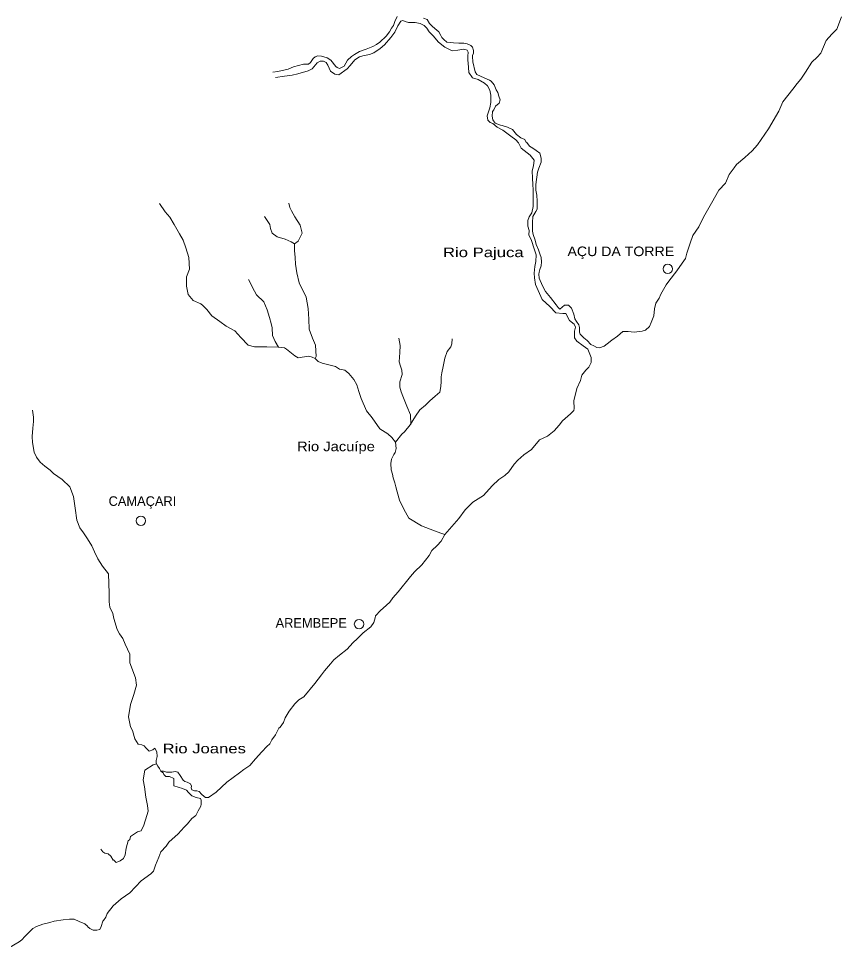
# Model space of a CAD drawing. Extents: x 47169 to 972804, y 7447977 to 9608469.
# Drawn here: x 564823 to 622022, y 8566017 to 8630617 of the extents above; entities that cross this region are included whole.
import ezdxf

# ---------------------------------------------------------------- set-up
doc = ezdxf.new("R2010")
doc.units = 0
doc.header["$LTSCALE"] = 270
doc.layers.add('1', color=7, linetype='Continuous', lineweight=13)
doc.layers.add('2', color=7, linetype='Continuous', lineweight=13)
doc.layers.add('3', color=7, linetype='Continuous')

msp = doc.modelspace()

# ---------------------------------------------------------------- linework, layer by layer
at = {"layer": '1'}
for points in [[(582501.5, 8626884.5), (582849.4, 8626927.8), (583556.5, 8627102.7), (583926.5, 8627256.4), (584622.8, 8627442.4), (584981.5, 8627441.4), (585123.2, 8627562.6), (585308.8, 8627838.5), (585428.7, 8627959.8), (585613.7, 8628014.6), (585885.4, 8628002.7), (586276.4, 8627879.9), (586536.8, 8627724.3), (586883.3, 8627280.9), (586970.1, 8627203.2), (587133, 8627147.4), (587448.7, 8627312.4), (587689.1, 8627720.8), (587972.5, 8627974.4), (588168.6, 8628128.6), (588528, 8628337.6), (588985.1, 8628491.1), (589442.2, 8628666.6), (589714.4, 8628820.6), (589943.2, 8628974.7), (590368.5, 8629393.7), (590608.6, 8629691.5), (590750.7, 8629945.4), (590892.7, 8630144.1), (590969.6, 8630409.2), (591144.7, 8630762.6)], [(592959.9, 8630646.2), (593231.3, 8630545.8), (593393.6, 8630279.9), (593599.4, 8630058), (593903, 8629813.7), (594044, 8629702.7), (594184.5, 8629436.8), (594249.3, 8629303.9), (594379.3, 8629159.7), (594585.2, 8628971), (595052.5, 8628925.2), (595422.1, 8628913), (595780.8, 8628911.8), (595998.1, 8628855.8), (596258.6, 8628733.2), (596377.8, 8628622.3), (596442.3, 8628400.8), (596441.7, 8628212.8), (596386.8, 8628047.1), (596375.6, 8627969.8), (596407, 8627604.7), (596556.9, 8626907.4), (596675.8, 8626719), (597196.9, 8626507.1), (597566, 8626340), (597663.6, 8626273.3), (597880.1, 8626007.1), (598031.1, 8625663.8), (598139.1, 8625464.3), (598203.6, 8625231.9), (598311.3, 8624955), (598223.6, 8624734.1), (597972.9, 8624535.9), (597852.5, 8624270.9), (597765.1, 8624149.5), (597753.1, 8623828.8), (597795.8, 8623574.3), (597958, 8623341.5), (598316.2, 8623207.6), (598435.7, 8623174), (598815.8, 8623073.1), (599163, 8622895), (599444.4, 8622551.2), (599726.2, 8622317.9), (600008.4, 8622206.4), (600083.9, 8622040.2), (600149, 8622006.8), (600343.7, 8621740.7), (600571.5, 8621607.2), (600810, 8621440.4), (601048.4, 8621251.6), (601155.9, 8620897.3), (601155, 8620631.9), (600990.5, 8620223.2), (600891.6, 8619925), (600780, 8619073.8), (600778.6, 8618686.7), (600842.6, 8618332.5), (600862.8, 8617912.2), (600861.6, 8617547.2), (600860.9, 8617359.2), (600773.4, 8617193.6), (600718.7, 8617083.2), (600576.6, 8616851.4), (600542.5, 8616431.3), (600540.4, 8615823)], [(600540.4, 8615823), (600604.8, 8615601.6), (600744.7, 8615202.9), (600808.8, 8614904.1), (600959.7, 8614538.6), (601056.4, 8614250.7), (601142.5, 8614007.1), (601163.2, 8613697.3), (601140.5, 8613432), (601063.5, 8613166.8), (601008.5, 8612990), (600986.3, 8612835.3), (601017.9, 8612558.7), (601244.2, 8612027), (601460.1, 8611628.1), (601806.3, 8611228.7), (602195.6, 8610718.6), (602336.2, 8610519), (602455.2, 8610396.9), (602618.7, 8610540.1), (602771.3, 8610683.3), (603042.9, 8610682.3), (603270.3, 8610471.4), (603410.1, 8610050.6), (603485, 8609740.6), (603603.8, 8609541.1), (603776.7, 8609308.2), (603808.7, 8609131.2), (603807.5, 8608799.4), (603872.2, 8608666.4), (604121.1, 8608411.1), (604348.6, 8608222.3), (604608.3, 8607944.8), (604803.5, 8607855.6), (605009.5, 8607744.3), (605204.9, 8607710.4), (605520.4, 8607830.9), (605738.3, 8607996), (606054.3, 8608249.2), (606457.3, 8608524.2), (606838.7, 8608843.5), (607208.1, 8608853.2), (607610, 8608818.5), (608164.2, 8608871.7), (608403.5, 8608948.2), (608676.1, 8609190.5), (608796.7, 8609477.6), (608972.3, 8609941.4), (609028.4, 8610427.9), (609116.8, 8610814.7), (609357.2, 8611178.7), (609467, 8611454.8), (609849.7, 8612094.8), (610013.7, 8612359.6), (610570.6, 8613076.4), (610942.1, 8613616.9), (611182.4, 8613936.7), (611281.6, 8614301.3), (611501.6, 8614986.2), (611699.3, 8615527.4), (612103.8, 8616134.1), (612443.3, 8616807.5), (612979.5, 8617767.6), (613504.8, 8618672.5), (613963.2, 8619179.4), (614226.4, 8619764.6), (614576, 8620238.8), (614740, 8620459.3), (615307.2, 8620965.8), (615808.9, 8621417.3), (616180.1, 8621825), (616945.5, 8622939), (617668, 8624185.9), (617942.4, 8624837.4), (618292.1, 8625278.3), (618652.6, 8625708.2), (618936.8, 8626094.2), (619198.9, 8626391.7), (619527.1, 8626888.1), (619975.7, 8627594.1), (620325, 8627924.4), (620598, 8628210.9), (620971.3, 8629083.1), (621364.5, 8629523.9), (621692.2, 8629887.5), (622022, 8630748.8)], [(600312.4, 8615879.1), (600226.5, 8616178), (600227.9, 8616576.2), (600315.7, 8616819.2), (600490.5, 8617106.1), (600589.9, 8617548.2), (600592.5, 8618289.2), (600583.1, 8618709.5), (600562.7, 8619085.6), (600542.5, 8619528), (600522.5, 8620025.8), (600610.6, 8620368.3), (600666.4, 8620777.4), (600374.1, 8621121.2), (599973.1, 8621443.4), (599767.2, 8621610), (599583.7, 8621964.5), (599399.6, 8622175.3), (599052.7, 8622441.9), (598488.9, 8622853.1), (598087.5, 8623064.6), (597784, 8623308.9), (597599.5, 8623398), (597447.9, 8623553.3), (597394.6, 8623863.2), (597592, 8624404.5), (597658.5, 8624769.2), (597649.4, 8625300.1), (597585.3, 8625632.1), (597412.4, 8625942.4), (597206.5, 8626131.1), (596772.5, 8626375.8), (596370.8, 8626498.8), (596122, 8626875.7), (596069.8, 8627539.4), (596059.5, 8627705.4), (596060.5, 8627992.9), (596083.1, 8628269.3), (596007.5, 8628424.4), (595768.6, 8628480.5), (595366.1, 8628415.5), (594963.7, 8628372.6), (594442.7, 8628617.6), (594009.1, 8628983.9), (593651.7, 8629427.5), (593359.1, 8629693.8), (593207.7, 8629948.7), (593023.5, 8630137.3), (592741.3, 8630282), (592393.6, 8630338.4), (591937, 8630350.9), (591698, 8630418), (591535.2, 8630484.9), (591404.5, 8630430), (591175.2, 8630121.1), (590989, 8629668.2), (590694.3, 8629293.1), (590257.9, 8628796.8), (589952.7, 8628532.3), (589527.8, 8628235), (589223.1, 8628125.4), (588744.5, 8628027.3), (588516, 8627961.6), (588200.1, 8627741.4), (587883.7, 8627355.3), (587654.6, 8627112.7), (587088.2, 8626705.2), (586805.7, 8626761.3), (586512.8, 8626950.2), (586329.2, 8627382.1), (586199.3, 8627559.4), (586014.8, 8627648.5), (585786.5, 8627649.1), (585579.7, 8627550.2), (585219.7, 8627119.9), (584958.4, 8626976.9), (584229.5, 8626768.9), (583837.9, 8626670.6), (583305, 8626605.7), (582685.2, 8626530.1)], [(594450.5, 8594741.7), (594168.4, 8594820.1), (593431, 8595110), (592834.6, 8595344.3), (591956.8, 8595878), (591708.3, 8596288), (591460.2, 8596775.4), (591309.3, 8597129.8), (591137.4, 8597694.4), (591051.6, 8598048.6), (590976.5, 8598325.4), (590869, 8598679.6), (590804.7, 8598934.2), (590729.7, 8599244.1), (590698.4, 8599664.5), (590742.9, 8599985.1), (590906.8, 8600305.3), (591005, 8600448.7), (591081.9, 8600713.9), (591029, 8601145.4), (590769.4, 8601489.1), (590487.8, 8601733.3), (589924.1, 8602077.9), (589405.2, 8602853.8), (589004.9, 8603341.6), (588627.4, 8604183.3), (588476.9, 8604681.5), (588337.1, 8605146.4), (588121, 8605523.1), (587785.6, 8605933.4), (587503.8, 8606166.5), (587134.8, 8606245), (586852.9, 8606411.8), (586483.8, 8606512.4), (585919.4, 8606657.9), (585637.3, 8606758.3), (585431.6, 8606980.1), (585236.3, 8607069.2), (584997.5, 8607136.2), (584541.1, 8607060.2), (584269.4, 8607016.8), (584030.8, 8607161.2), (583445.6, 8607616.4), (583304.7, 8607727.4), (582892, 8607761.8), (582088.2, 8607786.2), (581230, 8607777.6), (580785, 8607911.6), (580265, 8608432.8), (579853.5, 8608898.5), (579257, 8609231.9), (578812.4, 8609542.8), (578248.6, 8609953.6), (577913.1, 8610385.8), (577631.3, 8610663), (577490.4, 8610785.1), (576958.7, 8611007.7), (576601.3, 8611417.8), (576494.2, 8612004.3), (576506.8, 8612656.7), (576714.7, 8613198.1), (576651.7, 8614005.6), (576457.9, 8614680.7), (576252.8, 8615201), (576004.1, 8615644.1), (575636.4, 8616297.5), (575333.4, 8616796), (575008.4, 8617172.8), (574618.8, 8617760)], [(583999.4, 8614958.2), (584249.8, 8615145.5), (584359, 8615311.1), (584534, 8615697.6), (584405.2, 8616239.9), (584037.5, 8616838.2), (583788.8, 8617248.1), (583680.8, 8617480.7), (583616.5, 8617790.5)], [(585431.6, 8606980.1), (585508, 8607123.7), (585456, 8607898), (585251.1, 8608385.2), (585024.8, 8609016.3), (584994.3, 8609702.1), (584953.1, 8610454.2), (584814.2, 8611239.8), (584317.3, 8612236.7), (584167.2, 8612922.8), (584071.3, 8613542.4), (584040, 8613995.9), (584008.9, 8614493.7), (583999.4, 8614958.2), (583760.7, 8615080.6), (583348.3, 8615269.8), (582794.7, 8615448.3), (582447.7, 8615681.6), (582329.1, 8616024.8), (582286.4, 8616301.4), (581918.6, 8616844.3)], [(577548.8, 8576666.6), (577732.9, 8576522.3), (577819.5, 8576444.7), (578025.7, 8576455.2), (578569.2, 8576807.5), (579298.2, 8577513.3), (580189.8, 8578152.2), (580472.7, 8578383.6), (580896.7, 8578670), (581299.6, 8579133.3), (581735.1, 8579629.7), (582083.4, 8579993.7), (582279.3, 8580181.1), (582421.2, 8580457.2), (582671.8, 8580799.3), (582922.8, 8581263), (582999, 8581329.2), (583227.9, 8581671.3), (583359.1, 8581980.6), (583642.7, 8582455.3), (584034.9, 8582951.8), (584296.2, 8583227.6), (584655, 8583436.6), (585406.7, 8584374.4), (585875.3, 8584981.2), (586093.2, 8585246), (586507.2, 8585742.4), (586746.9, 8586018.2), (587138.7, 8586348.8), (587671.8, 8586756.3), (588064, 8587197.5), (588379.8, 8587506.2), (588771.8, 8587892), (589305.1, 8588321.7), (589512.3, 8588619.6), (589600.2, 8588951.1), (589622.3, 8589072.7), (589970.9, 8589458.7), (590166.8, 8589612.9), (590624.1, 8590020.6), (590842.2, 8590329.6), (591201.8, 8590737.7), (592063, 8591818.7), (592346.3, 8592127.5), (592847.3, 8592623.5), (593359.8, 8593274.3), (593545.5, 8593616.6), (593926.7, 8593969.2), (594199.2, 8594278), (594450.5, 8594741.7), (595431.5, 8595855.4), (595857, 8596451.2), (596390.9, 8596991.3), (597130.9, 8597442.3), (597741.3, 8598114.8), (598199, 8598566.7), (598623.5, 8598841.7), (598895.8, 8599084.1), (599277.9, 8599635.8), (599539.5, 8599911.3), (599953.5, 8600285.9), (600486.9, 8600638), (601043.2, 8601310.7), (601598.1, 8601585.2), (602055.6, 8601937.4), (602393.7, 8602334.4), (602633.8, 8602643.2), (603200.3, 8603127.8), (603418.3, 8603348.2), (603440.6, 8603503), (603420.8, 8604033.9), (603630.3, 8604895.8), (603882.2, 8605447.9), (603970.5, 8605823.6), (604254.2, 8606165.5), (604461.3, 8606374.8), (604614.6, 8606706.1), (604626.7, 8607037.8), (604389.8, 8607613.8), (604064.8, 8607847.3), (603631.4, 8608180.7), (603469.3, 8608413.5), (603460.1, 8608878.1), (603526.4, 8609165.4), (603451, 8609353.7), (603115.1, 8609609.2), (602856.1, 8610096.8), (602649.8, 8610108.6), (602171.8, 8610143.5), (601749.8, 8610598.5), (601230, 8611087), (600766.5, 8612128.2), (600681.1, 8612582), (600671.4, 8612913.8), (600705.7, 8613378.2), (600783, 8613731.8), (600806.3, 8614174.2), (600666.5, 8614606), (600483.8, 8615181.7), (600300.5, 8615580.5), (600312.4, 8615879.1)], [(582892, 8607761.8), (582665, 8608160.6), (582481.5, 8608581.3), (582450.5, 8609112.3), (582375.3, 8609400.1), (582257, 8609820.7), (582106.4, 8610363), (581869, 8610916.7), (581370.7, 8611404.7), (581089.7, 8611925.3), (580916.8, 8612268.6), (580808.7, 8612479)], [(591029, 8601145.4), (591465.2, 8601719.1), (591639.5, 8601873.4), (592053.8, 8602358.7), (592425.1, 8602965.8), (592708.9, 8603407.2), (593101, 8603726.7), (593406.1, 8604024.3), (593776.5, 8604354.9), (594103.2, 8604630.3), (594169.8, 8605039.3), (594203.4, 8605371), (594204.5, 8605691.7), (594238, 8605968.1), (594348.1, 8606410.1), (594447.8, 8606995.9), (594612.3, 8607470.9), (594863.2, 8607790.9), (594950.8, 8608000.7), (594973.7, 8608354.5)], [(592053.8, 8602358.7), (592086.5, 8602380.7), (592077.8, 8603066.4), (591819, 8603653.4), (591538.9, 8604362.2), (591409.5, 8604661.2), (591334.6, 8604993.2), (591335.7, 8605358.2), (591489.5, 8605866.4), (591468.7, 8606165.1), (591361, 8606453), (591285.9, 8606751.8), (591320.5, 8607393.2), (591354.7, 8607868.7), (591258.5, 8608388.8)], [(574721.1, 8578277.9), (574613.1, 8578466.3), (574494.1, 8578632.5), (574386.1, 8578820.8), (574397.5, 8579019.8), (574463.3, 8579285.1), (574431.7, 8579628), (574291.2, 8579871.7), (574149.8, 8579750.4), (573910.9, 8579673.6), (573672.8, 8579906.5), (573553.7, 8580039.5), (573380.3, 8580106.3), (573130.8, 8580162.3), (572903.8, 8580516.8), (572731.8, 8581114.4), (572613.1, 8581369.1), (572473.7, 8582044.1), (572595.4, 8582917.4), (572835.9, 8583602.5), (573022.1, 8584254.5), (572958.3, 8584763.4), (572559.5, 8585815.1), (572561, 8586423.4), (572237.1, 8587098.8), (572064.5, 8587497.4), (571848.2, 8587829.7), (571675.3, 8588117.7), (571449.3, 8588892.4), (571363.3, 8589235.5), (571158.2, 8589678.4), (571126.5, 8590043.4), (571117.2, 8590651.7), (571077.2, 8592001.1), (570666, 8592544), (570330.7, 8593042.5), (570103.9, 8593540.7), (569920.3, 8593950.4), (569617.5, 8594437.7), (569336.2, 8594847.6), (569076.5, 8595202.2), (568860.7, 8595733.5), (568754.1, 8596574.3), (568647.5, 8597381.8), (568388.5, 8598057.1), (567846.8, 8598567.1), (567261.3, 8598966.6), (567012.2, 8599210.5), (566643.6, 8599487.9), (566329.3, 8599765.1), (566058.6, 8600108.6), (565907.4, 8600462.8), (565800.3, 8601126.6), (565768.8, 8601558), (565813.5, 8602121.9), (565858.1, 8602597.3), (565858.7, 8602895.9), (565794.7, 8603382.7)], [(564188.7, 8566017.2), (564862.1, 8566413.8), (565046.8, 8566546.1), (565264.2, 8566777.8), (565514.3, 8567031.6), (565818.8, 8567340.6), (566068.6, 8567472.7), (566513.7, 8567626.4), (567002.1, 8567746.9), (567306, 8567845.7), (567913.7, 8567932.7), (568358.6, 8567986.9), (568684, 8567986.1), (569030.7, 8567830.4), (569420.8, 8567663.5), (569604.8, 8567497.2), (569648.1, 8567452.8), (569777.9, 8567341.9), (570005.4, 8567219.7), (570265.8, 8567219), (570472, 8567273.8), (570559.2, 8567461.6), (570668.7, 8567837.3), (570723, 8567892.5), (570897.2, 8568124.3), (570973.8, 8568367.4), (571398.2, 8568908.2), (571952.7, 8569404.5), (572561.3, 8569812.1), (573333.7, 8570639.5), (574007.6, 8571124.4), (574192.5, 8571322.9), (574334.7, 8571731.8), (574564, 8572295.2), (574706, 8572670.8), (575076, 8573068), (575272, 8573343.9), (575913.7, 8573928.3), (576338.1, 8574391.7), (576566.6, 8574601.2), (576860.6, 8574976.4), (577143.3, 8575196.8), (577296.1, 8575517.1), (577481.4, 8575848.4), (577514.4, 8575981), (577515.1, 8576257.5), (577461.2, 8576379.3), (577157.6, 8576446.5), (576875.8, 8576568.9), (576637.7, 8576801.8), (576497.1, 8576946), (576215.3, 8577079.5), (575608.1, 8577258.1), (575619.9, 8577612), (575620.3, 8577766.8), (575306, 8577911.4), (575067.3, 8577912.1), (574926.6, 8578045.2), (574905.1, 8578133.7), (574721.1, 8578277.9), (574894.7, 8578266.4), (575111.5, 8578210.6), (575274.3, 8578210.1), (575480.5, 8578209.6), (575708.4, 8578242.1), (575903.7, 8578197.3), (576065.8, 8577975.7), (576260.3, 8577654.5), (576379.4, 8577565.7), (576552.8, 8577509.9), (576780.4, 8577387.6), (576834.2, 8577243.7), (576812.2, 8577111), (576866.1, 8576978.2), (577061.2, 8576911.3), (577224, 8576910.8), (577386.6, 8576855.1), (577548.8, 8576666.6)], [(574386.1, 8578820.8), (574407.7, 8578787.5), (574179.6, 8578710.7), (573592.7, 8578336.2), (573482.4, 8577673), (573567.9, 8577175.1), (573663.7, 8576456), (573792.4, 8575891.6), (573823.9, 8575504.4), (573747.1, 8575183.9), (573539.2, 8574520.9), (573353.7, 8574123.2), (573082.3, 8574057.6), (572799.7, 8573870.3), (572604, 8573727.1), (572560.1, 8573517), (572440.5, 8573439.9), (572309, 8572920.5), (572231.8, 8572445.1), (572122.7, 8572202.1), (571894.5, 8572047.8), (571720.7, 8571959.8), (571612.1, 8571926.9), (571428.1, 8572104.3), (571395.5, 8572093.4), (571244.3, 8572359.2), (571049.5, 8572536.6), (570810.9, 8572581.5), (570670.1, 8572670.3), (570529.5, 8572847.6)]]:
    msp.add_lwpolyline(points, dxfattribs=at)
at = {"layer": '2'}
for centre, radius in [((609951.8, 8613211.5), 326.9), ((573323.2, 8595689.1), 330.7), ((588491.5, 8588501.2), 329.7)]:
    msp.add_circle(centre, radius, dxfattribs=at)

# ---------------------------------------------------------------- texts
at = {"layer": '3'}
for s, height, width, p in [('Rio Pajuca', 666.9, 1.3, (594324.9, 8614025.2)), ('AÇU DA TORRE', 666.9, 1.1, (602981.2, 8614096.6)), ('Rio Jacuípe', 666.6, 1.15, (584179.5, 8600527.2)), ('Rio Joanes', 666.1, 1.3, (574832.9, 8579516.3))]:
    msp.add_text(s, height=height, dxfattribs=dict(at, width=width)).set_placement(p)
for s, height, p in [('CAMAÇARI', 666.5, (571079.5, 8596725.4)), ('AREMBEPE', 666.3, (582689.6, 8588253.7))]:
    msp.add_text(s, height=height, dxfattribs=at).set_placement(p)

doc.saveas('drawing.dxf')
